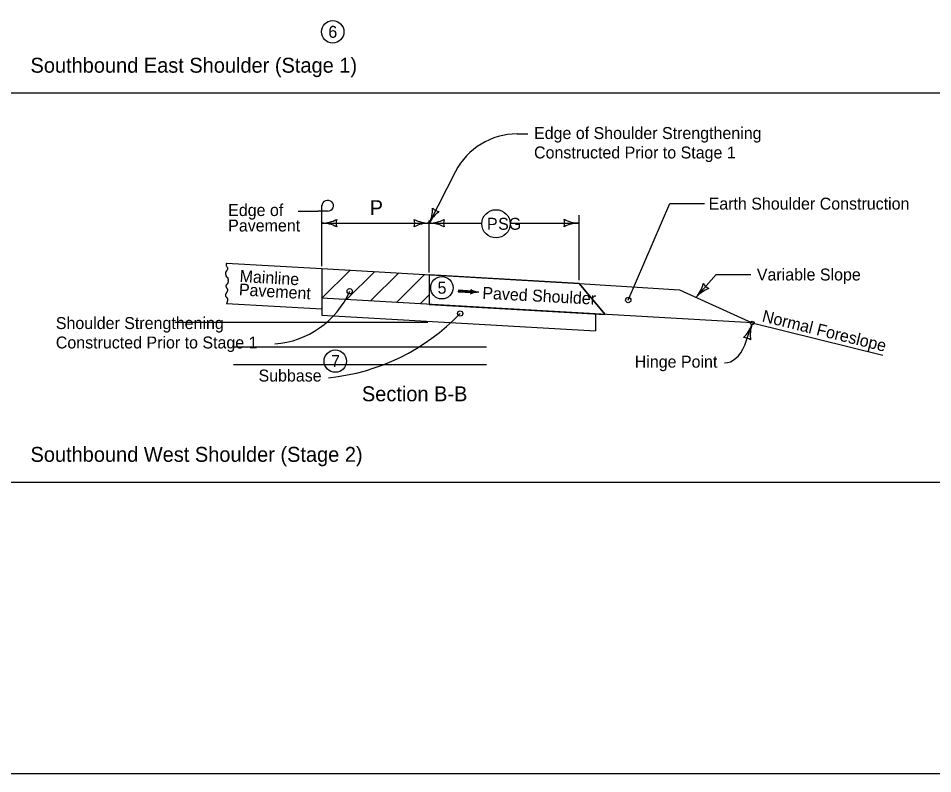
# Model space of a CAD drawing. Extents: x 8045 to 81668, y 6217 to 16762.
# Drawn here: x 11002 to 12226, y 7924 to 8935 of the extents above; entities that cross this region are included whole.
import ezdxf

# ---------------------------------------------------------------- set-up
doc = ezdxf.new("R2010")
doc.units = 0
for name, color, linetype in [('dsnStdDetailExtension', 7, 'Continuous'), ('dsnStdDimension', 7, 'Continuous'), ('dsnStdLabel', 7, 'Continuous'), ('dsnStdLineWork', 7, 'Continuous'), ('dsnStdPattern', 7, 'Continuous'), ('dsnStdSection', 7, 'Continuous'), ('Level 4', 7, 'Continuous'), ('Level 8', 7, 'Continuous')]:
    doc.layers.add(name, color=color, linetype=linetype)

msp = doc.modelspace()

# ---------------------------------------------------------------- linework, layer by layer
at = {"layer": 'dsnStdDetailExtension'}
for centre in [(11446, 8570), (11446, 8570), (11818.9, 8558.2), (11818.9, 8558.2), (11593.9, 8540.2), (11593.9, 8540.2)]:
    msp.add_circle(centre, 3.54, dxfattribs=at)
at = {"layer": 'dsnStdDimension'}
msp.add_line((10152.2, 8314.4), (13247.9, 8314.4), dxfattribs=at)
at = {"layer": 'dsnStdLabel'}
for p, q in [((11281.2, 8607.8), (11408.7, 8600.4)), ((11408.7, 8600.4), (11408.7, 8546.4)), ((11408.7, 8600.4), (11753, 8580.4)), ((11552.4, 8592.1), (11552.4, 8552.2)), ((11752.5, 8580.6), (11752.5, 8580.6)), ((11753, 8580.5), (11887.7, 8572.1)), ((11753, 8580.4), (11788, 8539)), ((11887.7, 8572.1), (11984.8, 8527.6)), ((11984.8, 8527.6), (11408.7, 8560.8)), ((11281.2, 8553.8), (11408.7, 8546.4)), ((11408.7, 8546.4), (11408.7, 8538)), ((11775.2, 8554.1), (11775.2, 8554.1)), ((11408.7, 8538), (11775.2, 8516.9)), ((11775.2, 8539.7), (11775.2, 8516.9)), ((11212, 8528.5), (11550.5, 8528.5)), ((11984.8, 8527.6), (12159.8, 8484.3)), ((11290.6, 8495.5), (11629.1, 8495.5)), ((11290.6, 8471.8), (11629.1, 8471.8))]:
    msp.add_line(p, q, dxfattribs=at)
msp.add_ellipse((11984.8, 8527.6), major_axis=(2.58, 0), ratio=0.913811, dxfattribs=at)
for points in [[(11281.2, 8607.8), (11280.7, 8604.2), (11281.8, 8602.7), (11282.6, 8600.4), (11282, 8598.4), (11280.1, 8596), (11279.6, 8594.1), (11280.1, 8591.8), (11281, 8589.4), (11282, 8588.7), (11283.4, 8586.2), (11283.4, 8585.3)], [(11281.4, 8568.2), (11281.6, 8568.5), (11281.8, 8568.7), (11282.2, 8569.3), (11282.5, 8569.9), (11282.6, 8570.2), (11282.7, 8570.5), (11282.8, 8571.1), (11282.9, 8571.7), (11282.8, 8572.3), (11282.8, 8572.6), (11282.7, 8572.7), (11282.7, 8572.9), (11282.5, 8573.2), (11282.2, 8573.6), (11281.9, 8574), (11281.6, 8574.4), (11281.5, 8574.7), (11281.4, 8574.9), (11281.1, 8575.5), (11280.9, 8576.1), (11280.8, 8576.4), (11280.8, 8576.7), (11280.8, 8576.8), (11280.8, 8576.9), (11280.9, 8577.7), (11281.1, 8578.2), (11281.4, 8578.7), (11281.8, 8579.4), (11282.3, 8579.9), (11282.9, 8580.5), (11283.1, 8580.8), (11283.3, 8581.1), (11283.5, 8581.6), (11283.6, 8582.1), (11283.8, 8582.5), (11283.8, 8582.8), (11283.8, 8582.9), (11283.8, 8583), (11283.8, 8583.5), (11283.6, 8584), (11283.6, 8584.2), (11283.5, 8584.3), (11283.5, 8584.4), (11283.4, 8584.5), (11283.4, 8585.3)], [(11281.4, 8568.2), (11281.2, 8568), (11281, 8567.8), (11280.7, 8567.5), (11280.5, 8567.2), (11280.4, 8567), (11280.3, 8566.7), (11280, 8566.1), (11279.9, 8565.8), (11279.8, 8565.5), (11279.7, 8565.2), (11279.7, 8565.1), (11279.7, 8564.9), (11279.7, 8564.4), (11279.8, 8563.9), (11280, 8563.4), (11280.3, 8562.9), (11280.7, 8562.2), (11281.3, 8561.7), (11281.8, 8561.2), (11282, 8560.8), (11282.2, 8560.5), (11282.6, 8559.6), (11282.7, 8559.1), (11282.7, 8558.6), (11282.7, 8558.3), (11282.6, 8558), (11282.6, 8557.7), (11282.5, 8557.5), (11282.2, 8556.3), (11282, 8555.7), (11281.8, 8555.1), (11281.6, 8554.5), (11281.5, 8554.2), (11281.3, 8553.9), (11281.2, 8553.8)]]:
    msp.add_spline(points, degree=3, dxfattribs=at)
at = {"layer": 'dsnStdLineWork'}
for p, q in [((11670.1, 8780.7), (11684.4, 8780.7)), ((11587.8, 8730.3), (11552.4, 8661.2)), ((11408.7, 8664.5), (11408.7, 8685.3)), ((11818.9, 8558.2), (11874.6, 8687.3)), ((11874.6, 8687.3), (11921, 8687.3)), ((11377.3, 8677.3), (11404, 8677.3)), ((11416.5, 8677.3), (11404, 8677.3)), ((11753, 8585), (11753, 8671.7)), ((11408.7, 8603.6), (11408.7, 8664.5)), ((11408.7, 8661.2), (11623, 8661.2)), ((11552.4, 8594.9), (11552.4, 8664.5)), ((11660.8, 8661.3), (11753, 8661.3)), ((11408.7, 8560.8), (11446.5, 8598.2)), ((11441.7, 8558.9), (11479.5, 8596.3)), ((11474, 8557.1), (11511.8, 8594.5)), ((11508.6, 8555.1), (11546.4, 8592.5)), ((11909.9, 8561.9), (11936.5, 8592.4)), ((11936.5, 8592.4), (11982.9, 8592.4)), ((11609.7, 8569.3), (11591.5, 8570.4)), ((11609.6, 8568.4), (11609.6, 8568.4)), ((11609.7, 8570.3), (11609.7, 8570.3)), ((11540.2, 8553.2), (11552.4, 8565.4)), ((11975, 8497.7), (11984.5, 8525.3))]:
    msp.add_line(p, q, dxfattribs=at)
for points in [[(11609.7, 8570.3), (11591.6, 8571.3), (11591.4, 8569.4), (11609.6, 8568.4), (11609.7, 8570), (11591.8, 8571.1), (11591.7, 8569.6), (11609.2, 8568.6), (11609.3, 8569.8), (11592, 8570.8), (11592, 8569.8), (11609, 8568.8), (11609.1, 8569.5), (11592.2, 8570.6), (11592.2, 8570), (11608.8, 8569.1)], [(11609.3, 8571.5), (11610, 8570.3), (11610, 8568.7), (11609.2, 8567.3), (11612, 8568.2), (11615.2, 8568.8), (11616.1, 8568.9), (11613.8, 8569.5), (11610.6, 8570.7), (11609.7, 8571.3), (11609.8, 8567.7), (11614.7, 8569), (11610.1, 8570.5), (11610.1, 8568.1), (11613.5, 8569.1), (11610.5, 8569.9), (11610.3, 8568.5), (11612.4, 8569), (11610.9, 8569.5), (11610.7, 8568.9), (11611.5, 8569)]]:
    msp.add_lwpolyline(points, dxfattribs=at)
msp.add_circle((11641.9, 8660.3), 18.9, dxfattribs=at)
for centre, radius, start, end in [((11670.1, 8688.3), 92.4, 90, 152.9341), ((11514.6, 8680.5), 42.5, 332.9341, 1.0066), ((11568.7, 8692.9), 16.4, 225.2008, 260.6675), ((11408.7, 8703.7), 42.5, 270, 298.0725), ((11444.3, 8661.2), 16.4, 162.2666, 197.7334), ((11516.8, 8661.2), 16.4, 342.2666, 17.7334), ((11552.4, 8703.7), 42.5, 241.9275, 270), ((11590.3, 8641.8), 42.5, 124.8616, 152.9341), ((11552.4, 8703.7), 42.5, 270, 298.0725), ((11588.1, 8661.2), 16.4, 162.2666, 197.7334), ((11717.3, 8661.3), 16.4, 342.2666, 17.7333), ((11753, 8703.8), 42.5, 241.9275, 270), ((11408.7, 8618.7), 42.5, 61.9275, 90), ((11552.4, 8618.7), 42.5, 90, 118.0725), ((11552.4, 8618.7), 42.5, 61.9275, 90), ((11753, 8618.8), 42.5, 90, 118.0725), ((11877.9, 8589.9), 42.5, 318.8454, 346.9178), ((11933.4, 8588.8), 16.4, 211.112, 246.5787), ((11337.4, 8618.2), 118.9, 274.0851, 336.0699), ((11941.9, 8534), 42.5, 110.7729, 138.8454), ((11390, 8734.9), 282, 275.6784, 316.2844), ((11944.3, 8539.1), 42.5, 312.9788, 341.0513), ((12024.7, 8511.5), 42.5, 161.0513, 189.1238), ((11972.9, 8491.6), 16.4, 53.3179, 88.7846)]:
    msp.add_arc(centre, radius, start, end, dxfattribs=at)
for centre, major_axis, ratio, start_param, end_param in [((11416.5, 8684.5), (-7.81, 0), 0.913811, 1.570796, 6.283185), ((11605.9, 8569.5), (3.88, 0), 0.913811, 5.202895, 7.237436), ((11618.2, 8548.5), (22.2, 0), 0.913811, 1.537172, 2.061295), ((11621, 8588.9), (-22.2, 0), 0.913811, 0.954258, 1.478381), ((11947.9, 8535.5), (0, 61.5), 0.559383, 3.141593, 4.048985)]:
    msp.add_ellipse(centre, major_axis=major_axis, ratio=ratio, start_param=start_param, end_param=end_param, dxfattribs=at)
at = {"layer": 'dsnStdPattern'}
for p, q in [((11552.5, 8592.1), (11552.4, 8552.2)), ((11753, 8580.5), (11552.5, 8592.1)), ((11788, 8539), (11753, 8580.5)), ((11552.4, 8552.2), (11788, 8539))]:
    msp.add_line(p, q, dxfattribs=at)
at = {"layer": 'dsnStdSection'}
msp.add_lwpolyline([(10132.5, 9944), (13267.5, 9944), (13267.5, 7924), (10132.5, 7924)], close=True, dxfattribs=at)
at = {"layer": 'Level 4'}
msp.add_line((12307.8, 8835.4), (10152.2, 8835.4), dxfattribs=at)
at = {"layer": 'Level 8'}
for centre in [(11423.3, 8917.3), (11569.5, 8574.7), (11426.8, 8476.5)]:
    msp.add_circle(centre, 15, dxfattribs=at)

# ---------------------------------------------------------------- texts
at = {"layer": 'dsnStdLineWork'}
for s, height, p in [('Southbound East Shoulder (Stage 1)', 20, (11018.8, 8862.6)), ('Edge of Shoulder Strengthening', 16, (11692.8, 8773.8)), ('Constructed Prior to Stage 1', 16, (11692.8, 8747.8)), ('P', 20, (11472.8, 8671.9)), ('Earth Shoulder Construction', 16, (11926.5, 8679.3)), ('Edge of ', 16, (11283.4, 8670.7)), ('Pavement', 16, (11283.4, 8650)), ('P', 16, (11629.8, 8652.3)), ('SG', 16, (11644.7, 8652.3)), ('Variable Slope', 16, (11991, 8584.4)), ('Shoulder Strengthening', 16, (11052.7, 8519.4)), ('Constructed Prior to Stage 1', 16, (11052.7, 8493.4)), ('Hinge Point', 16, (11827.6, 8467.7)), ('Subbase', 16, (11324, 8449.1)), ('Section B-B', 20, (11462.4, 8422.7)), ('Southbound West Shoulder (Stage 2)', 20, (11018.8, 8341.6))]:
    msp.add_text(s, height=height, dxfattribs=at).set_placement(p)
for s, rotation, p in [('Mainline', 356.7346, (11298.4, 8582.5)), ('Pavement', 356.7346, (11297.4, 8564.5)), ('Paved Shoulder ', 356.983, (11623.3, 8560)), ('Normal Foreslope', 346.0988, (11997, 8529.7))]:
    msp.add_text(s, height=16, rotation=rotation, dxfattribs=at).set_placement(p)
at = {"layer": 'Level 8'}
for s, p in [('6', (11417.5, 8909.3)), ('5', (11563.7, 8566.7)), ('7', (11421.1, 8468.5))]:
    msp.add_text(s, height=16, dxfattribs=at).set_placement(p)

doc.saveas('drawing.dxf')
